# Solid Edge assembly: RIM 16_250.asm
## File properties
Title: Zylinder
Author: ahadarics
Template: iso metric assembly.asm
Last saved by: ahadarics
Revision: 20
Application: Solid Edge
Username: ahadarics
Dokumentum tartalom típus: 1
Document Number: RIM 16/250
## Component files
Profilrohr.par
Kolbenstange.par
Kit_1.par
Kit_2.par
Mutter_1.par
Mutter_2.par
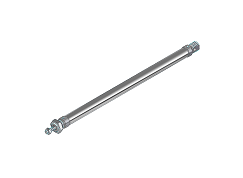
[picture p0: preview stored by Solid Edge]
